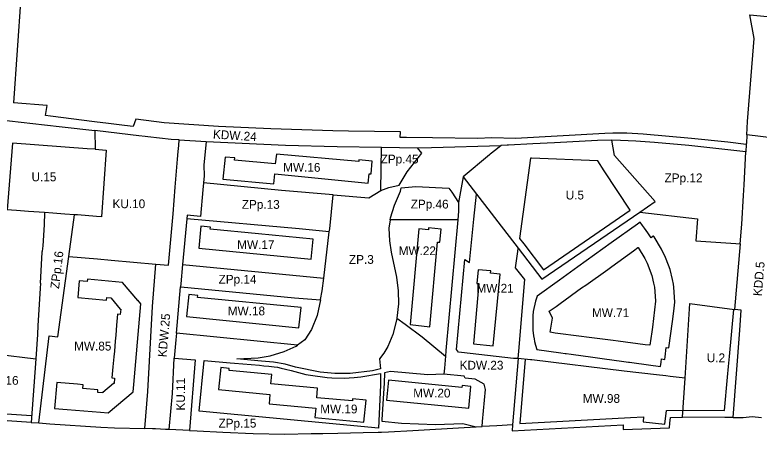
# Model space of a CAD drawing. Extents: x 7424434 to 7425898, y 5541432 to 5542659.
# Drawn here: x 7424993.9 to 7425417.1, y 5541850.5 to 5542089.1 of the extents above; entities that cross this region are included whole.
import ezdxf

# ---------------------------------------------------------------- set-up
doc = ezdxf.new("R2010")
doc.units = 0
for name, color, linetype in [('linie rozgraniczające', 7, 'Continuous'), ('nieprzekraczalne linie zabudowy', 7, 'Continuous'), ('obowiazujace linie zabudowy', 7, 'Continuous'), ('przeznaczenia terenów', 7, 'Continuous')]:
    doc.layers.add(name, color=color, linetype=linetype)

msp = doc.modelspace()

# ---------------------------------------------------------------- linework, layer by layer
at = {"layer": 'linie rozgraniczające'}
for p, q in [((7424997.54, 5542100.77), (7424993.13, 5542039.11)), ((7425414.29, 5542075.65), (7425411.87, 5542089.11)), ((7425411.87, 5542089.11), (7425421.8, 5542088.13)), ((7425410.55, 5542028.37), (7425414.29, 5542075.65)), ((7425012.26, 5542037.62), (7424993.13, 5542039.11)), ((7425011.43, 5542031.8), (7425012.26, 5542037.62)), ((7424984.02, 5542029.59), (7425010.84, 5542026.55)), ((7425014.15, 5542031.46), (7425011.43, 5542031.8)), ((7425039.28, 5542028.27), (7425014.15, 5542031.46)), ((7425062.75, 5542029.68), (7425061.18, 5542025.62)), ((7425078.8, 5542027.72), (7425062.75, 5542029.68)), ((7425010.84, 5542026.55), (7425020.8, 5542025.42)), ((7425020.8, 5542025.42), (7425039.39, 5542023.26)), ((7425047.16, 5542027.27), (7425039.28, 5542028.27)), ((7425056.31, 5542026.11), (7425047.16, 5542027.27)), ((7425061.18, 5542025.62), (7425056.31, 5542026.11)), ((7425109.8, 5542025.65), (7425078.8, 5542027.72)), ((7425139.49, 5542024.29), (7425109.8, 5542025.65)), ((7425410.14, 5542020.92), (7425410.55, 5542028.37)), ((7425039.39, 5542023.26), (7425039.61, 5542012.61)), ((7425047.25, 5542022.35), (7425039.39, 5542023.26)), ((7425064.51, 5542020.35), (7425047.25, 5542022.35)), ((7425174.66, 5542023.09), (7425139.49, 5542024.29)), ((7425183.55, 5542022.87), (7425174.66, 5542023.09)), ((7425213.17, 5542022.5), (7425183.55, 5542022.87)), ((7425213.08, 5542019.35), (7425213.17, 5542022.5)), ((7425329.37, 5542021.66), (7425278.57, 5542018.83)), ((7425333.94, 5542021.84), (7425329.37, 5542021.66)), ((7425341.98, 5542021.71), (7425333.94, 5542021.84)), ((7425351.16, 5542021.25), (7425341.98, 5542021.71)), ((7425378.75, 5542018.82), (7425351.16, 5542021.25)), ((7425410.14, 5542020.92), (7425409.87, 5542016.01)), ((7425432.08, 5542018.07), (7425410.14, 5542020.93)), ((7425067.98, 5542019.95), (7425064.51, 5542020.35)), ((7425069.58, 5542019.77), (7425067.98, 5542019.95)), ((7425082.85, 5542018.23), (7425069.58, 5542019.77)), ((7425087.34, 5542017.96), (7425082.85, 5542018.23)), ((7425087.08, 5542014.79), (7425087.34, 5542017.96)), ((7425087.34, 5542017.96), (7425102.64, 5542017.02)), ((7425102.64, 5542017.02), (7425101.34, 5542003.5)), ((7425102.64, 5542017.02), (7425147.9, 5542014.93)), ((7425216.58, 5542019.3), (7425213.08, 5542019.35)), ((7425231.41, 5542019.09), (7425216.58, 5542019.3)), ((7425257.03, 5542018.73), (7425231.41, 5542019.09)), ((7425265.18, 5542019.21), (7425257.03, 5542018.73)), ((7425278.57, 5542018.83), (7425265.18, 5542019.21)), ((7425325.14, 5542017.68), (7425300.83, 5542016.34)), ((7425333.35, 5542017.9), (7425325.14, 5542017.68)), ((7425338.25, 5542017.7), (7425333.35, 5542017.9)), ((7425334.89, 5542009.07), (7425333.35, 5542017.9)), ((7425347.04, 5542017.32), (7425338.25, 5542017.7)), ((7425357.66, 5542016.49), (7425347.04, 5542017.32)), ((7425399.29, 5542016.59), (7425378.75, 5542018.82)), ((7425409.83, 5542015.36), (7425399.29, 5542016.59)), ((7425039.61, 5542012.61), (7425045.9, 5542012.15)), ((7425086.8, 5542011.31), (7425087.08, 5542014.79)), ((7425147.9, 5542014.93), (7425177.2, 5542014.16)), ((7425177.2, 5542014.16), (7425202.4, 5542013.79)), ((7425201.99, 5541989.14), (7425202.4, 5542013.79)), ((7425202.4, 5542013.79), (7425222.96, 5542013.49)), ((7425222.96, 5542013.49), (7425230.88, 5542013.58)), ((7425225.25, 5542010.48), (7425222.96, 5542013.49)), ((7425230.88, 5542013.58), (7425270.35, 5542014.71)), ((7425267.44, 5542012.4), (7425264.13, 5542009.84)), ((7425270.35, 5542014.71), (7425267.44, 5542012.4)), ((7425273.82, 5542014.89), (7425270.35, 5542014.71)), ((7425274.53, 5542014.93), (7425273.82, 5542014.89)), ((7425288.37, 5542015.67), (7425274.53, 5542014.93)), ((7425300.83, 5542016.34), (7425288.37, 5542015.67)), ((7425377.22, 5542014.71), (7425357.66, 5542016.49)), ((7425409.6, 5542011.19), (7425377.22, 5542014.71)), ((7425409.83, 5542015.36), (7425409.6, 5542011.19)), ((7425409.83, 5542015.36), (7425409.87, 5542016.01)), ((7425045.9, 5542012.15), (7425043.15, 5541974.25)), ((7425086.46, 5542007.06), (7425086.8, 5542011.31)), ((7425217.08, 5541999.79), (7425225.25, 5542010.48)), ((7425263.76, 5542009.55), (7425248.8, 5541996.99)), ((7425264.13, 5542009.84), (7425263.76, 5542009.55)), ((7425358.03, 5541982.83), (7425334.89, 5542009.07)), ((7425408.56, 5541992.35), (7425409.6, 5542011.19)), ((7425085.17, 5541991.05), (7425086.46, 5542007.06)), ((7425101.34, 5542003.5), (7425101.55, 5541997.55)), ((7425212.41, 5541992.27), (7425217.08, 5541999.79)), ((7425101.55, 5541997.55), (7425101.17, 5541993.59)), ((7425248.8, 5541996.99), (7425246.23, 5541982.41)), ((7425248.8, 5541996.99), (7425256.38, 5541987.13)), ((7425101.17, 5541993.59), (7425100.78, 5541989.63)), ((7425145.55, 5541989.13), (7425101.17, 5541993.59)), ((7425206.5, 5541990.95), (7425212.41, 5541992.27)), ((7425213.6, 5541990.72), (7425221.94, 5541991.47)), ((7425221.94, 5541991.47), (7425240.71, 5541990.43)), ((7425408.22, 5541986.35), (7425408.56, 5541992.35)), ((7425083.86, 5541975.87), (7425085.17, 5541991.05)), ((7425100.78, 5541989.63), (7425099.47, 5541974.43)), ((7425174.9, 5541986.69), (7425145.55, 5541989.13)), ((7425195.27, 5541984.99), (7425201.99, 5541989.14)), ((7425201.99, 5541989.14), (7425206.5, 5541990.95)), ((7425209.76, 5541980.86), (7425213.16, 5541988.88)), ((7425213.16, 5541988.88), (7425213.6, 5541990.72)), ((7425240.71, 5541990.43), (7425242.46, 5541988.29)), ((7425242.46, 5541988.29), (7425246.23, 5541982.41)), ((7425254.94, 5541972.77), (7425256.38, 5541987.13)), ((7425256.38, 5541987.13), (7425260.92, 5541981.22)), ((7425172.93, 5541967.44), (7425174.9, 5541986.69)), ((7425174.9, 5541986.69), (7425195.27, 5541984.99)), ((7425349.33, 5541976.86), (7425358.03, 5541982.83)), ((7425407.31, 5541969.95), (7425408.22, 5541986.35)), ((7425207.46, 5541973.69), (7425209.76, 5541980.86)), ((7425246.23, 5541982.41), (7425246.24, 5541977.39)), ((7425260.92, 5541981.22), (7425268.46, 5541971.4)), ((7424994.88, 5541977.76), (7424986.31, 5541978.38)), ((7425001.77, 5541977.26), (7424994.88, 5541977.76)), ((7425010.86, 5541976.59), (7425001.77, 5541977.26)), ((7425010.86, 5541976.59), (7425010.53, 5541969.71)), ((7425015.53, 5541976.26), (7425010.86, 5541976.59)), ((7425022.41, 5541975.76), (7425015.53, 5541976.26)), ((7425027.87, 5541975.36), (7425022.41, 5541975.76)), ((7425024.63, 5541951.63), (7425027.87, 5541975.36)), ((7425029.49, 5541975.24), (7425027.87, 5541975.36)), ((7425040.4, 5541974.45), (7425029.49, 5541975.24)), ((7425043.15, 5541974.25), (7425040.4, 5541974.45)), ((7425081.24, 5541946.64), (7425083.86, 5541975.87)), ((7425091.83, 5541975.17), (7425091.63, 5541972.96)), ((7425099.47, 5541974.43), (7425091.83, 5541975.17)), ((7425246.24, 5541977.39), (7425245.79, 5541972.43)), ((7425293.62, 5541938.65), (7425349.33, 5541976.86)), ((7425349.33, 5541976.86), (7425381.99, 5541972.98)), ((7425091.63, 5541972.96), (7425089.32, 5541947.14)), ((7425155.55, 5541967.27), (7425091.63, 5541972.96)), ((7425207.28, 5541972.43), (7425206.59, 5541967.72)), ((7425207.28, 5541972.43), (7425207.46, 5541973.69)), ((7425240.55, 5541972.43), (7425207.28, 5541972.43)), ((7425245.79, 5541972.43), (7425239.03, 5541898.12)), ((7425245.79, 5541972.43), (7425240.55, 5541972.43)), ((7425252.48, 5541948.23), (7425254.94, 5541972.77)), ((7425268.46, 5541971.4), (7425280.07, 5541956.29)), ((7425381.99, 5541972.98), (7425381.16, 5541960.49)), ((7425010.53, 5541969.71), (7425009.8, 5541957.71)), ((7425172.73, 5541965.74), (7425155.55, 5541967.27)), ((7425172.73, 5541965.74), (7425172.93, 5541967.44)), ((7425206.59, 5541967.72), (7425206.9, 5541960.54)), ((7425406.33, 5541958.75), (7425407.31, 5541969.95)), ((7425169.55, 5541939.31), (7425172.73, 5541965.74)), ((7425009.8, 5541957.71), (7425009.55, 5541954.57)), ((7425206.9, 5541960.54), (7425207.87, 5541954)), ((7425381.16, 5541960.49), (7425403.94, 5541958.92)), ((7425406.33, 5541958.75), (7425403.04, 5541921.5)), ((7425403.94, 5541958.92), (7425406.33, 5541958.75)), ((7425008.47, 5541936.39), (7425009.51, 5541954)), ((7425009.51, 5541954), (7425009.54, 5541954.44)), ((7425009.55, 5541954.57), (7425009.54, 5541954.44)), ((7425207.87, 5541954), (7425210.84, 5541939.8)), ((7425278.59, 5541945.15), (7425279.82, 5541954.47)), ((7425279.82, 5541954.47), (7425280.07, 5541956.29)), ((7425280.07, 5541956.29), (7425293.62, 5541938.65)), ((7425018.38, 5541905.88), (7425024.63, 5541951.63)), ((7425024.63, 5541951.63), (7425040.9, 5541950.22)), ((7425040.9, 5541950.22), (7425048.7, 5541949.55)), ((7425048.7, 5541949.55), (7425074.05, 5541947.28)), ((7425245.1, 5541898.62), (7425249.77, 5541949.93)), ((7425249.77, 5541949.93), (7425252.48, 5541948.23)), ((7425072.12, 5541923.23), (7425074.05, 5541947.28)), ((7425074.05, 5541947.28), (7425081.24, 5541946.64)), ((7425089.32, 5541947.14), (7425088.33, 5541936.09)), ((7425089.32, 5541947.14), (7425169.55, 5541939.31)), ((7425283.98, 5541938.59), (7425278.59, 5541945.15)), ((7425008.47, 5541936.39), (7425008.28, 5541933.32)), ((7425168.69, 5541932.16), (7425169.55, 5541939.31)), ((7425210.84, 5541939.8), (7425211.92, 5541932.06)), ((7425280.42, 5541897.84), (7425283.98, 5541938.59)), ((7425008.28, 5541933.32), (7425007.03, 5541912.36)), ((7425085.85, 5541908), (7425088.18, 5541934.43)), ((7425088.33, 5541936.09), (7425088.18, 5541934.43)), ((7425088.18, 5541934.43), (7425088.22, 5541934.43)), ((7425088.22, 5541934.43), (7425152.94, 5541928.08)), ((7425167.79, 5541927.19), (7425168.69, 5541932.16)), ((7425211.92, 5541932.06), (7425212, 5541924.65)), ((7425152.94, 5541928.08), (7425167.73, 5541926.87)), ((7425167.72, 5541926.87), (7425165.74, 5541918.01)), ((7425167.73, 5541926.87), (7425167.79, 5541927.19)), ((7425212, 5541924.65), (7425211.03, 5541916.59)), ((7425375.01, 5541882.31), (7425377.74, 5541924.79)), ((7425377.74, 5541924.79), (7425403.04, 5541921.5)), ((7425069.54, 5541874.75), (7425072.12, 5541923.23)), ((7425406.94, 5541920.99), (7425403.04, 5541921.5)), ((7425406.11, 5541909.69), (7425406.94, 5541920.99)), ((7425165.74, 5541918.01), (7425162.61, 5541910.06)), ((7425210.88, 5541915.33), (7425208.87, 5541907.2)), ((7425211.03, 5541916.59), (7425210.88, 5541915.33)), ((7425211.03, 5541916.59), (7425215.89, 5541913.09)), ((7425007.03, 5541912.36), (7425006.72, 5541907.24)), ((7425215.89, 5541913.09), (7425225.52, 5541905.96)), ((7425006.72, 5541907.24), (7425005.9, 5541893.39)), ((7425085.85, 5541908), (7425085.51, 5541904.21)), ((7425154.55, 5541901.13), (7425085.85, 5541908)), ((7425162.61, 5541910.06), (7425158.72, 5541904.18)), ((7425208.87, 5541907.2), (7425206, 5541900.42)), ((7425402.38, 5541860.01), (7425406.11, 5541909.69)), ((7425007.57, 5541856.9), (7425013.4, 5541906.44)), ((7425013.4, 5541906.44), (7425018.38, 5541905.88)), ((7425085.51, 5541904.21), (7425084.58, 5541893.83)), ((7425158.72, 5541904.18), (7425154.55, 5541901.13)), ((7425225.52, 5541905.96), (7425238.75, 5541894.92)), ((7425146.98, 5541897.6), (7425153.88, 5541900.64)), ((7425153.88, 5541900.64), (7425154.55, 5541901.13)), ((7425206, 5541900.42), (7425203.76, 5541896.57)), ((7425239.03, 5541898.12), (7425239.02, 5541898.03)), ((7425246.22, 5541897.26), (7425245.1, 5541898.62)), ((7424974.32, 5541897.1), (7425005.9, 5541893.39)), ((7425084.57, 5541893.73), (7425084.58, 5541893.83)), ((7425084.58, 5541893.83), (7425084.59, 5541893.83)), ((7425084.59, 5541893.83), (7425096.47, 5541892.83)), ((7425120.14, 5541893.43), (7425132.32, 5541893.95)), ((7425132.32, 5541893.95), (7425139.13, 5541895.11)), ((7425139.13, 5541895.11), (7425146.98, 5541897.6)), ((7425203.76, 5541896.57), (7425201.25, 5541893.43)), ((7425238.75, 5541894.92), (7425238.16, 5541888)), ((7425239.02, 5541898.03), (7425238.75, 5541894.92)), ((7425247.83, 5541897.07), (7425246.22, 5541897.26)), ((7425277.39, 5541893.54), (7425247.83, 5541897.07)), ((7425280.07, 5541893.51), (7425280.42, 5541897.84)), ((7425005.9, 5541893.39), (7425003.17, 5541857.12)), ((7425083.59, 5541873.63), (7425084.57, 5541893.73)), ((7425096.47, 5541892.83), (7425093.23, 5541852.55)), ((7425098.64, 5541863.64), (7425101.49, 5541892.4)), ((7425101.49, 5541892.4), (7425116.38, 5541891.14)), ((7425116.38, 5541891.14), (7425118.87, 5541890.84)), ((7425118.87, 5541890.84), (7425133.07, 5541889.71)), ((7425134.11, 5541892.14), (7425120.14, 5541893.43)), ((7425133.07, 5541889.71), (7425135.58, 5541889.47)), ((7425140.99, 5541891.5), (7425134.11, 5541892.14)), ((7425147.63, 5541890.27), (7425140.99, 5541891.5)), ((7425153.49, 5541888.69), (7425147.63, 5541890.27)), ((7425201.25, 5541893.43), (7425201.86, 5541887.63)), ((7425280.07, 5541893.51), (7425276.94, 5541855.85)), ((7425280.07, 5541893.51), (7425277.39, 5541893.54)), ((7425287.15, 5541892.81), (7425280.07, 5541893.51)), ((7425287.88, 5541892.73), (7425287.15, 5541892.81)), ((7425340.28, 5541886.46), (7425287.88, 5541892.73)), ((7425135.58, 5541889.47), (7425138.41, 5541889.27)), ((7425138.41, 5541889.27), (7425141.43, 5541888.91)), ((7425141.43, 5541888.91), (7425143.26, 5541888.6)), ((7425143.26, 5541888.6), (7425145.29, 5541888)), ((7425145.29, 5541888), (7425147.8, 5541887.46)), ((7425147.8, 5541887.46), (7425151.01, 5541886.77)), ((7425151.01, 5541886.77), (7425159.41, 5541884.56)), ((7425167.45, 5541885.81), (7425153.49, 5541888.69)), ((7425175.81, 5541884.99), (7425167.45, 5541885.81)), ((7425197.32, 5541886.54), (7425184.58, 5541885.01)), ((7425201.86, 5541887.63), (7425197.32, 5541886.54)), ((7425204.04, 5541885.37), (7425203.83, 5541879.51)), ((7425207.48, 5541886.27), (7425204.04, 5541885.37)), ((7425228.77, 5541884.33), (7425207.48, 5541886.27)), ((7425238.16, 5541888), (7425237.8, 5541884.64)), ((7425358.8, 5541884.24), (7425340.28, 5541886.46)), ((7425159.41, 5541884.56), (7425162.12, 5541884)), ((7425162.12, 5541884), (7425171.59, 5541882.67)), ((7425171.59, 5541882.67), (7425174.2, 5541882.48)), ((7425174.2, 5541882.48), (7425181.08, 5541882.4)), ((7425184.58, 5541885.01), (7425175.81, 5541884.99)), ((7425181.08, 5541882.4), (7425186.78, 5541882.75)), ((7425186.78, 5541882.75), (7425190.59, 5541883.16)), ((7425190.59, 5541883.16), (7425201.84, 5541884.98)), ((7425201.84, 5541884.98), (7425201.8, 5541878.49)), ((7425237.8, 5541884.64), (7425228.77, 5541884.33)), ((7425249.35, 5541883.53), (7425237.8, 5541884.64)), ((7425249.99, 5541882.39), (7425249.35, 5541883.53)), ((7425255.7, 5541881.83), (7425249.99, 5541882.39)), ((7425260.77, 5541879.02), (7425255.7, 5541881.83)), ((7425364.02, 5541883.62), (7425358.8, 5541884.24)), ((7425366.44, 5541883.33), (7425364.02, 5541883.62)), ((7425375.01, 5541882.31), (7425366.44, 5541883.33)), ((7425373.59, 5541860.22), (7425375.01, 5541882.31)), ((7425201.8, 5541878.49), (7425200.68, 5541853.92)), ((7425203.83, 5541879.51), (7425202.65, 5541858.9)), ((7425261.54, 5541875.96), (7425260.77, 5541879.02)), ((7425067.8, 5541853.73), (7425069.54, 5541874.75)), ((7425081.67, 5541853.14), (7425083.59, 5541873.63)), ((7425259.83, 5541857.65), (7425261.54, 5541875.96)), ((7425200.68, 5541853.92), (7425098.64, 5541863.64)), ((7425366.35, 5541856.85), (7425366.68, 5541860.04)), ((7425366.68, 5541860.04), (7425373.59, 5541860.22)), ((7425397.54, 5541860.04), (7425373.59, 5541860.22)), ((7425402.38, 5541860.01), (7425397.54, 5541860.04)), ((7425402.38, 5541860.01), (7425408.06, 5541859.97)), ((7425408.06, 5541859.97), (7425413.19, 5541860.48)), ((7425413.19, 5541860.48), (7425418.37, 5541860.04)), ((7425003.17, 5541857.12), (7424971.91, 5541859.31)), ((7425003.17, 5541857.12), (7425007.57, 5541856.9)), ((7425007.57, 5541856.9), (7425013.83, 5541856.46)), ((7425013.83, 5541856.46), (7425042.89, 5541854.42)), ((7425202.65, 5541858.9), (7425202.6, 5541857.9)), ((7425202.6, 5541857.9), (7425213.76, 5541856.8)), ((7425213.76, 5541856.8), (7425233.06, 5541856.05)), ((7425233.06, 5541856.05), (7425248.66, 5541856.58)), ((7425248.66, 5541856.58), (7425256.19, 5541854.67)), ((7425259.57, 5541854.86), (7425259.83, 5541857.65)), ((7425276.94, 5541855.85), (7425268.06, 5541855.35)), ((7425276.94, 5541855.85), (7425276.65, 5541852.37)), ((7425276.65, 5541852.37), (7425339.79, 5541855.79)), ((7425339.79, 5541855.79), (7425339.73, 5541853.12)), ((7425366.07, 5541854.17), (7425366.35, 5541856.85)), ((7425042.89, 5541854.42), (7425050.59, 5541854.21)), ((7425050.59, 5541854.21), (7425067.8, 5541853.73)), ((7425067.82, 5541853.73), (7425067.8, 5541853.73)), ((7425072.14, 5541853.62), (7425067.82, 5541853.73)), ((7425073.98, 5541853.53), (7425072.14, 5541853.62)), ((7425079.66, 5541853.24), (7425073.98, 5541853.53)), ((7425081.67, 5541853.14), (7425079.66, 5541853.24)), ((7425093.23, 5541852.55), (7425081.67, 5541853.14)), ((7425093.23, 5541852.55), (7425097.52, 5541852.33)), ((7425097.52, 5541852.33), (7425112.09, 5541851.59)), ((7425112.09, 5541851.59), (7425129.34, 5541850.82)), ((7425191.88, 5541851.41), (7425200.58, 5541851.68)), ((7425200.58, 5541851.68), (7425202.32, 5541851.73)), ((7425202.32, 5541851.73), (7425206.31, 5541851.85)), ((7425206.31, 5541851.85), (7425220.23, 5541852.63)), ((7425220.23, 5541852.63), (7425249.37, 5541854.29)), ((7425249.37, 5541854.29), (7425256.19, 5541854.67)), ((7425256.19, 5541854.67), (7425256.31, 5541854.68)), ((7425256.31, 5541854.68), (7425259.57, 5541854.86)), ((7425268.06, 5541855.35), (7425259.57, 5541854.86)), ((7425339.73, 5541853.12), (7425366.07, 5541854.17)), ((7425129.34, 5541850.82), (7425147.44, 5541850.54)), ((7425147.44, 5541850.54), (7425162.47, 5541850.84)), ((7425162.47, 5541850.84), (7425169.04, 5541850.97)), ((7425169.04, 5541850.97), (7425177.66, 5541851.14)), ((7425177.66, 5541851.14), (7425191.88, 5541851.41))]:
    msp.add_line(p, q, dxfattribs=at)
at = {"layer": 'nieprzekraczalne linie zabudowy'}
for points in [[(7425039.61, 5542012.61), (7425034.97, 5542012.95), (7424992.66, 5542016.02), (7424989.51, 5541978.15)], [(7425373.85, 5541864.22), (7425397.4, 5541864.04), (7425399.18, 5541882.94), (7425399.7, 5541888.98), (7425400.24, 5541894.77), (7425402.69, 5541921.55)], [(7424963.21, 5541898.41), (7424961.01, 5541864.08), (7424972.19, 5541863.3), (7425003.4, 5541861.11)], [(7425284.06, 5541893.14), (7425281.02, 5541856.61), (7425343.89, 5541860.02), (7425351.41, 5541860.4), (7425351.09, 5541857.54), (7425363.58, 5541856.16), (7425364.45, 5541863.98), (7425373.85, 5541864.23)]]:
    msp.add_lwpolyline(points, dxfattribs=at)
msp.add_lwpolyline([(7425329.04, 5542000.35), (7425325.31, 5542006.02), (7425287.6, 5542007.54), (7425287.19, 5542007.56), (7425280.81, 5541961.89), (7425283.24, 5541958.73), (7425294.48, 5541944.09), (7425343.83, 5541977.94)], close=True, dxfattribs=at)
at = {"layer": 'obowiazujace linie zabudowy'}
for points in [[(7425112.24, 5541995.66), (7425141.1, 5541992.89), (7425141.76, 5541998.57), (7425194.86, 5541993.41), (7425195.45, 5541998.73), (7425196.5, 5541998.64), (7425197.17, 5542005.91), (7425189.52, 5542006.62), (7425189.42, 5542005.63), (7425142.7, 5542009.94), (7425141.99, 5542004.33), (7425118.84, 5542006.37), (7425118.95, 5542007.77), (7425113.58, 5542008.23)], [(7425098.58, 5541956.28), (7425162.34, 5541950.06), (7425163.48, 5541961.39), (7425132.5, 5541964.48), (7425105.06, 5541967.13), (7425105.18, 5541968.32), (7425099.73, 5541968.85)], [(7425218.63, 5541912.86), (7425229.84, 5541911.62), (7425234.33, 5541959.8), (7425235.61, 5541959.68), (7425236.31, 5541967.22), (7425229.21, 5541967.88), (7425229.11, 5541966.78), (7425223.69, 5541967.29)], [(7425254.62, 5541901.86), (7425265.91, 5541900.79), (7425269.84, 5541941.55), (7425264.43, 5541942.07), (7425264.54, 5541943.39), (7425257.39, 5541944.1), (7425256.54, 5541936.33), (7425257.77, 5541936.21)], [(7425029.5, 5541878.91), (7425017.87, 5541879.93), (7425016.54, 5541865.13), (7425023.7, 5541864.5), (7425042.72, 5541863.02), (7425046.95, 5541862.64), (7425061.13, 5541874.55), (7425061.5, 5541878.78), (7425065.14, 5541920.36), (7425065.51, 5541924.61), (7425063.93, 5541926.71), (7425063.82, 5541926.61), (7425055.16, 5541936.83), (7425035.16, 5541938.63), (7425035.06, 5541937.4), (7425030.58, 5541937.79), (7425029.73, 5541928.27), (7425046.13, 5541926.82), (7425046.27, 5541928.32), (7425048.71, 5541928.1), (7425048.69, 5541927.84), (7425053.83, 5541921.71), (7425054.1, 5541921.69), (7425053.82, 5541918.6), (7425052.33, 5541918.74), (7425051.78, 5541912.49), (7425051.28, 5541906.78), (7425051, 5541903.52), (7425050.5, 5541897.82), (7425050.21, 5541894.56), (7425049.71, 5541888.86), (7425049.15, 5541882.6), (7425050.65, 5541882.47), (7425050.38, 5541879.4), (7425050.1, 5541879.43), (7425043.88, 5541874.21), (7425043.86, 5541874.02), (7425041.07, 5541874.27), (7425041.2, 5541875.75), (7425032.65, 5541876.51), (7425032.84, 5541878.62)], [(7425091.43, 5541917.49), (7425155.48, 5541911.09), (7425156.68, 5541922.62), (7425097.8, 5541928.31), (7425097.91, 5541929.47), (7425092.78, 5541929.97)], [(7425109.8, 5541876.01), (7425138.96, 5541873.16), (7425138.59, 5541867.8), (7425165.04, 5541865.3), (7425164.56, 5541859.96), (7425192.39, 5541857.42), (7425193.7, 5541869.92), (7425186, 5541870.65), (7425185.89, 5541869.45), (7425165.58, 5541871.26), (7425166.06, 5541876.63), (7425139.46, 5541879.17), (7425139.99, 5541884.39), (7425115.69, 5541886.66), (7425115.81, 5541887.91), (7425111.01, 5541888.44)], [(7425205.21, 5541869.89), (7425252, 5541865.23), (7425253.21, 5541877.7), (7425248.23, 5541878.18), (7425248.12, 5541876.98), (7425206.37, 5541881.21)]]:
    msp.add_lwpolyline(points, close=True, dxfattribs=at)
for points in [[(7425288.43, 5541909.72), (7425288.81, 5541906.5), (7425289.14, 5541904.72), (7425289.41, 5541903.19), (7425289.98, 5541901.15), (7425290.78, 5541898.63), (7425304.3, 5541896.79), (7425306.9, 5541896.43), (7425307.46, 5541896.35), (7425310.17, 5541895.98), (7425322.49, 5541894.32), (7425327.81, 5541893.6), (7425340.2, 5541891.92), (7425342.84, 5541891.56), (7425343.42, 5541891.48), (7425345.99, 5541891.13), (7425361.05, 5541889.08), (7425361.37, 5541891.42), (7425361.64, 5541893.3), (7425362.48, 5541893.15), (7425363.41, 5541892.98), (7425363.6, 5541894.48), (7425364.3, 5541899.89), (7425365.76, 5541899.71), (7425367.85, 5541914.66), (7425368.63, 5541920.56), (7425369.16, 5541925.6), (7425368.69, 5541934.14), (7425368.39, 5541935.78), (7425367.89, 5541938.44), (7425366.58, 5541944.3), (7425365.52, 5541946.77), (7425363.91, 5541951.1), (7425361.69, 5541955.72), (7425357.35, 5541962.8), (7425357.09, 5541963.22), (7425356.93, 5541963.1), (7425355.66, 5541962.16), (7425353.75, 5541965.05), (7425351.98, 5541967.65), (7425350.86, 5541969.21), (7425349.47, 5541971.14), (7425347.88, 5541970), (7425332.98, 5541959.32), (7425314.1, 5541945.69), (7425303.52, 5541938.14), (7425290.96, 5541929.09), (7425289.98, 5541926.17), (7425288.71, 5541920.41), (7425288.42, 5541917.93), (7425288.43, 5541909.72)], [(7425298.35, 5541908.49), (7425299.64, 5541916.56), (7425297.76, 5541920.5), (7425301.63, 5541923.21), (7425303.99, 5541924.86), (7425316.2, 5541933.72), (7425318.56, 5541935.35), (7425331.11, 5541944.31), (7425333.42, 5541946), (7425345.71, 5541954.9), (7425348.06, 5541956.67), (7425348.26, 5541956.81), (7425352.05, 5541950.44), (7425353.38, 5541947.85), (7425356.01, 5541940.86), (7425356.97, 5541936.49), (7425357.53, 5541934.08), (7425358.01, 5541929.13), (7425358.1, 5541926.15), (7425356.43, 5541911.47), (7425356.07, 5541908.8), (7425355.03, 5541901.11), (7425352.27, 5541901.44), (7425337.05, 5541903.45), (7425334.19, 5541903.79), (7425319.03, 5541905.78), (7425316.19, 5541906.14), (7425301.19, 5541908.08), (7425298.35, 5541908.49)]]:
    msp.add_lwpolyline(points, dxfattribs=at)

# ---------------------------------------------------------------- texts
at = {"layer": 'przeznaczenia terenów'}
for s, rotation, p in [('KDW.24', 356.4942, (7425106.45, 5542018.77)), ('ZPp.16', 83.2065, (7425019.03, 5541932.99)), ('KDD.5', 85, (7425418.59, 5541928.89)), ('KDW.25', 85, (7425080.14, 5541894.16)), ('KU.11', 90, (7425090.66, 5541863.96))]:
    msp.add_text(s, height=5, rotation=rotation, dxfattribs=at).set_placement(p)
for s, p in [('ZPp.45', (7425201.9, 5542004.57)), ('MW.16', (7425146.5, 5541999.82)), ('U.15', (7425003.42, 5541994.42)), ('ZPp.12', (7425363.34, 5541993.85)), ('U.5', (7425307.13, 5541984.08)), ('KU.10', (7425049.46, 5541979.12)), ('ZPp.13', (7425122.97, 5541978.75)), ('ZPp.46', (7425219.01, 5541978.93)), ('MW.17', (7425120.35, 5541955.87)), ('MW.22', (7425212.17, 5541952.39)), ('ZP.3', (7425183.89, 5541947.44)), ('ZPp.14', (7425109.77, 5541936.18)), ('MW.21', (7425256.39, 5541931.05)), ('MW.18', (7425115, 5541918.14)), ('MW.71', (7425322.08, 5541917.1)), ('MW.85', (7425027.64, 5541898.12)), ('U.2', (7425387.36, 5541891.47)), ('KDW.23', (7425246.82, 5541887.26)), ('U.16', (7424981.92, 5541878.63)), ('MW.20', (7425220.43, 5541871.4)), ('MW.98', (7425316.84, 5541868.33)), ('MW.19', (7425167.55, 5541862.33)), ('ZPp.15', (7425109.72, 5541854.25))]:
    msp.add_text(s, height=5, dxfattribs=at).set_placement(p)

doc.saveas('drawing.dxf')
